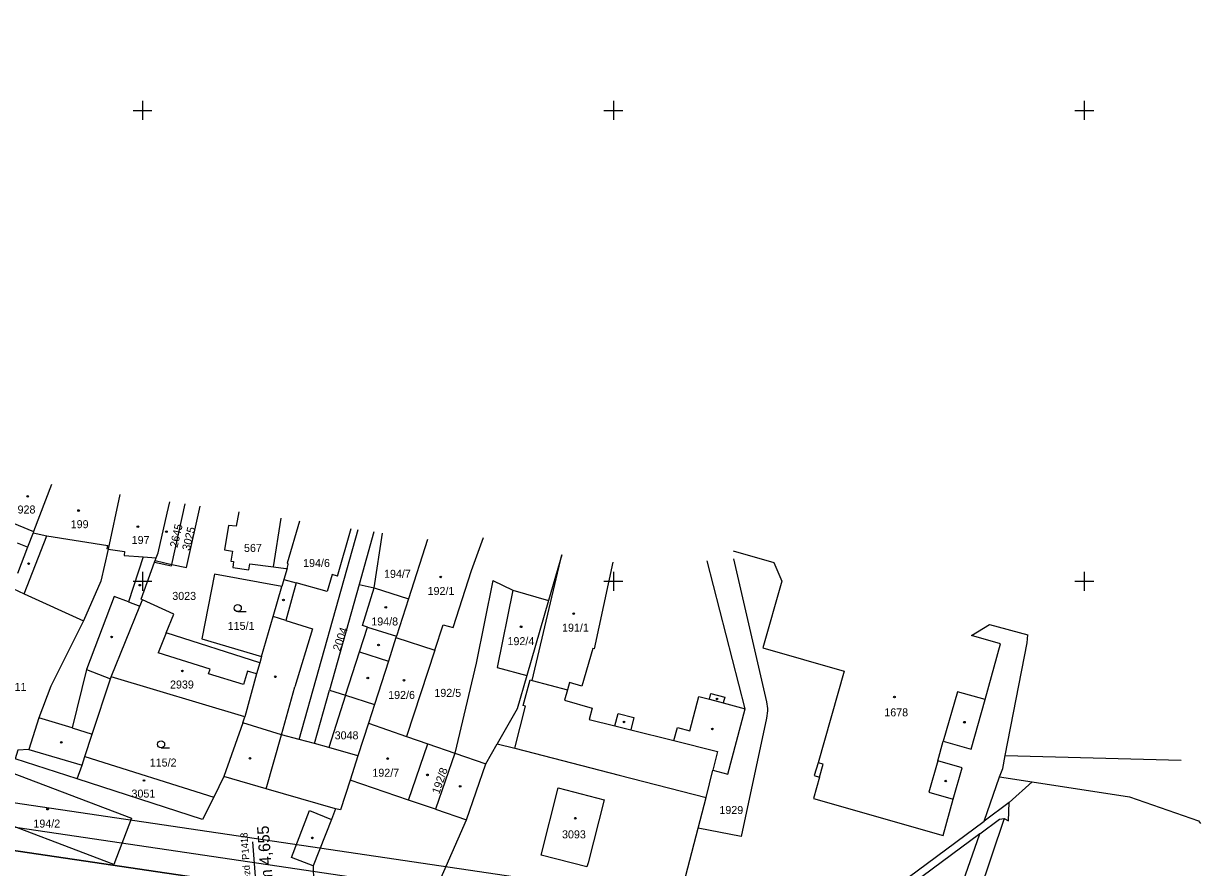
# Model space of a CAD drawing. Extents: x -779302 to -774398, y -1144902 to -1142831.
# Drawn here: x -774925.2 to -774675.3, y -1144360.8 to -1144181.6 of the extents above; entities that cross this region are included whole.
import ezdxf

# ---------------------------------------------------------------- set-up
doc = ezdxf.new("R2010")
doc.units = 0
for name, color, linetype in [('hektosit - Vrstva 5', 7, 'Continuous'), ('Hranice parcel', 7, 'Continuous'), ('Parcelní čísla', 7, 'Continuous'), ('Vnitřní kresba', 7, 'Continuous'), ('Vrstva 1', 7, 'Continuous'), ('zjednodus_g_situ-seda - Vrstva 4', 7, 'Continuous'), ('Značky budov', 7, 'Continuous'), ('Značky kultur', 7, 'Continuous')]:
    doc.layers.add(name, color=color, linetype=linetype)

msp = doc.modelspace()

# ---------------------------------------------------------------- linework, layer by layer
at = {"layer": 'hektosit - Vrstva 5'}
for p, q in [((-774900, -1144198), (-774900, -1144202)), ((-774800, -1144198), (-774800, -1144202)), ((-774700, -1144198), (-774700, -1144202)), ((-774902, -1144200), (-774898, -1144200)), ((-774802, -1144200), (-774798, -1144200)), ((-774702, -1144200), (-774698, -1144200)), ((-774900, -1144298), (-774900, -1144302)), ((-774800, -1144298), (-774800, -1144302)), ((-774700, -1144298), (-774700, -1144302)), ((-774902, -1144300), (-774898, -1144300)), ((-774802, -1144300), (-774798, -1144300)), ((-774702, -1144300), (-774698, -1144300))]:
    msp.add_line(p, q, dxfattribs=at)
at = {"layer": 'Hranice parcel'}
for p, q in [((-774893.78, -1144296.41), (-774890.92, -1144283.59)), ((-774866.73, -1144333.6), (-774854.2, -1144289.03)), ((-774850.85, -1144289.52), (-774853.99, -1144300.71)), ((-774839.44, -1144291.11), (-774843.52, -1144303.75)), ((-774810.96, -1144294.39), (-774813.77, -1144304.08)), ((-774853.99, -1144300.71), (-774860.29, -1144323.14)), ((-774846.16, -1144311.97), (-774837.89, -1144314.64)), ((-774837.89, -1144314.64), (-774843.96, -1144332.95)), ((-774874.7, -1144315.99), (-774875.08, -1144317.3)), ((-774878.28, -1144328.8), (-774906.64, -1144320.27)), ((-774863.47, -1144334.48), (-774860.29, -1144323.14)), ((-774850.74, -1144326.17), (-774852.02, -1144330.16)), ((-774878.71, -1144330.05), (-774878.28, -1144328.8)), ((-774852.02, -1144330.16), (-774854.24, -1144337.04)), ((-774852.02, -1144330.16), (-774843.96, -1144332.95)), ((-774863.47, -1144334.48), (-774866.73, -1144333.6)), ((-774843.96, -1144332.95), (-774839.41, -1144334.53)), ((-774843.47, -1144346.47), (-774839.41, -1144334.53)), ((-774839.41, -1144334.53), (-774833.68, -1144336.52)), ((-774912.2, -1144337.19), (-774884.85, -1144345.82)), ((-774854.24, -1144337.04), (-774855.92, -1144342.24)), ((-774716.78, -1144337.02), (-774679.41, -1144338.01)), ((-774913.86, -1144341.97), (-774927, -1144337.72)), ((-774843.47, -1144346.47), (-774855.92, -1144342.24)), ((-774721.28, -1144350.96), (-774718.02, -1144341.55)), ((-774782, -1144352.41), (-774780.31, -1144345.89))]:
    msp.add_line(p, q, dxfattribs=at)
for points in [[(-774919.28, -1144279.44), (-774923.12, -1144289.46), (-774923.21, -1144289.71), (-774924.38, -1144292.76), (-774926.52, -1144298.36)], [(-774904.78, -1144281.6), (-774907.28, -1144293.19), (-774908.84, -1144299.98), (-774912.54, -1144308.38)], [(-774897.4, -1144295.94), (-774897.28, -1144295.62), (-774897.07, -1144295.04), (-774896.68, -1144293.96), (-774894.72, -1144285.56), (-774894.18, -1144283.12)], [(-774893.78, -1144296.41), (-774890.67, -1144297.11), (-774887.75, -1144284.05)], [(-774879.56, -1144285.28), (-774880.06, -1144288.28), (-774881.72, -1144288.14), (-774882.56, -1144293.33), (-774880.89, -1144293.6), (-774881.2, -1144295.73), (-774880.63, -1144295.81), (-774880.81, -1144297.08), (-774877.38, -1144297.6), (-774877.2, -1144296.27), (-774872.18, -1144296.96), (-774869.53, -1144297.29), (-774869.28, -1144297.32)], [(-774869.28, -1144297.32), (-774869.02, -1144296.42), (-774869.19, -1144296.07), (-774866.6, -1144287.19)], [(-774837.89, -1144314.64), (-774836.11, -1144309.23), (-774834.01, -1144309.82), (-774830.14, -1144297.71), (-774827.58, -1144290.74)], [(-774774.57, -1144293.53), (-774765.9, -1144296.02), (-774764.22, -1144299.97), (-774768.29, -1144314.14), (-774750.98, -1144319.11), (-774756.51, -1144338.56), (-774757.38, -1144341.25), (-774756.2, -1144341.59), (-774757.5, -1144346.11), (-774730, -1144353.97), (-774727.82, -1144346.25), (-774725.92, -1144339.62), (-774731.12, -1144338.14), (-774729.94, -1144333.99), (-774724.02, -1144335.67), (-774721.09, -1144325.13), (-774717.77, -1144313.27), (-774723.95, -1144311.51), (-774720.12, -1144309.16), (-774712, -1144311.41)], [(-774900.01, -1144303.91), (-774900.24, -1144303.82), (-774897.4, -1144295.94)], [(-774897.4, -1144295.94), (-774893.86, -1144296.73), (-774893.78, -1144296.41)], [(-774774.48, -1144295.25), (-774767.47, -1144325.61), (-774767.27, -1144327.04), (-774767.26, -1144327.55), (-774767.48, -1144329.1), (-774772.89, -1144354.17), (-774782, -1144352.41)], [(-774780.31, -1144345.89), (-774778.87, -1144340.14), (-774775.69, -1144340.97), (-774772.03, -1144327.08), (-774780.09, -1144295.65)], [(-774870.37, -1144301.08), (-774884.68, -1144298.48), (-774887.41, -1144312.22), (-774874.7, -1144315.99)], [(-774869.28, -1144297.32), (-774869.95, -1144299.63), (-774870.37, -1144301.08)], [(-774927.54, -1144301.56), (-774925.13, -1144302.69), (-774912.54, -1144308.38)], [(-774874.7, -1144315.99), (-774872.23, -1144307.48), (-774870.37, -1144301.08)], [(-774853.99, -1144300.71), (-774850.78, -1144301.42), (-774843.52, -1144303.75)], [(-774825.63, -1144299.86), (-774829.16, -1144317.4), (-774833.68, -1144336.52)], [(-774825.63, -1144299.86), (-774821.36, -1144301.89), (-774813.77, -1144304.08)], [(-774906.64, -1144320.27), (-774900.57, -1144305.31), (-774900.01, -1144303.91)], [(-774875.08, -1144317.3), (-774894.95, -1144310.97), (-774893.3, -1144306.99), (-774900.01, -1144303.91)], [(-774843.52, -1144303.75), (-774846.07, -1144311.68), (-774846.16, -1144311.97)], [(-774813.77, -1144304.08), (-774818.37, -1144320.02), (-774820.43, -1144327.09), (-774824.66, -1144334.51)], [(-774912.54, -1144308.38), (-774919.42, -1144322.31), (-774922.03, -1144328.99), (-774924.14, -1144335.71), (-774926.42, -1144335.89), (-774927, -1144337.72)], [(-774846.16, -1144311.97), (-774847.76, -1144316.94), (-774850.74, -1144326.17)], [(-774716.78, -1144337.02), (-774712.11, -1144313.08), (-774712, -1144311.41)], [(-774875.08, -1144317.3), (-774875.75, -1144319.63), (-774878.28, -1144328.8)], [(-774912.2, -1144337.19), (-774910.64, -1144332.46), (-774906.8, -1144320.74), (-774906.64, -1144320.27)], [(-774860.29, -1144323.14), (-774856.87, -1144324.2), (-774850.74, -1144326.17)], [(-774878.71, -1144330.05), (-774882.69, -1144341.48), (-774884.85, -1144345.82)], [(-774866.73, -1144333.6), (-774870.5, -1144332.58), (-774878.71, -1144330.05)], [(-774854.24, -1144337.04), (-774860.45, -1144335.29), (-774863.47, -1144334.48)], [(-774845.62, -1144383.56), (-774831.16, -1144350.65), (-774827.09, -1144338.8), (-774824.66, -1144334.51)], [(-774824.66, -1144334.51), (-774820.92, -1144335.47), (-774798.77, -1144341.16), (-774780.31, -1144345.89)], [(-774913.86, -1144341.97), (-774912.82, -1144339.08), (-774912.2, -1144337.19)], [(-774833.68, -1144336.52), (-774837.74, -1144348.41), (-774843.47, -1144346.47)], [(-774718.02, -1144341.55), (-774717.33, -1144339.74), (-774716.78, -1144337.02)], [(-774902.35, -1144350.28), (-774906.07, -1144360.14), (-774935.48, -1144349), (-774931.84, -1144339.13), (-774902.35, -1144350.28)], [(-774884.85, -1144345.82), (-774887.22, -1144350.6), (-774913.86, -1144341.97)], [(-774855.92, -1144342.24), (-774857.95, -1144348.55), (-774858.99, -1144348.34), (-774859.86, -1144350.58), (-774863.72, -1144360.44), (-774863.41, -1144376.75), (-774845.62, -1144383.56)], [(-774718.02, -1144341.55), (-774711.1, -1144342.61), (-774690.44, -1144345.78), (-774675.74, -1144350.91), (-774675.34, -1144351.41)], [(-774805.38, -1144359.83), (-774805.62, -1144360.66), (-774815.36, -1144358.16), (-774811.7, -1144343.89), (-774801.96, -1144346.39), (-774805.38, -1144359.83)], [(-774722.22, -1144353.64), (-774717.98, -1144350.5), (-774717.01, -1144350.41), (-774716.11, -1144350.89), (-774715.95, -1144347), (-774721.28, -1144350.96)], [(-774801.98, -1144406.47), (-774799.57, -1144406.26), (-774796.3, -1144405.69), (-774793.89, -1144404.6), (-774791.79, -1144403.24), (-774759.55, -1144379.36), (-774721.28, -1144350.96)], [(-774722.22, -1144353.64), (-774758.58, -1144380.6), (-774790.75, -1144404.47), (-774793.02, -1144405.95), (-774795.8, -1144407.18), (-774799.56, -1144407.9), (-774820.31, -1144409.63), (-774822.18, -1144410.3), (-774823.4, -1144411.16), (-774824.38, -1144412.31), (-774825.86, -1144415.63)], [(-774804.69, -1144399.57), (-774793.9, -1144398.06), (-774782, -1144352.41)], [(-774739.17, -1144384.29), (-774735.41, -1144376.57), (-774726.72, -1144366.58), (-774722.22, -1144353.64)]]:
    msp.add_lwpolyline(points, dxfattribs=at)
at = {"layer": 'Vnitřní kresba'}
for p, q in [((-774929.64, -1144286.74), (-774923.12, -1144289.46)), ((-774872.18, -1144296.96), (-774870.57, -1144286.6)), ((-774923.21, -1144289.71), (-774920.27, -1144290.35)), ((-774858.55, -1144298.94), (-774855.71, -1144288.79)), ((-774850.78, -1144301.42), (-774849.03, -1144289.78)), ((-774924.38, -1144292.76), (-774926.53, -1144291.93)), ((-774925.13, -1144302.69), (-774920.27, -1144290.35)), ((-774920.27, -1144290.35), (-774907.36, -1144292.41)), ((-774907.5, -1144293.14), (-774907.36, -1144292.41)), ((-774907.28, -1144293.19), (-774907.5, -1144293.14)), ((-774907.28, -1144293.19), (-774903.81, -1144293.67)), ((-774903.81, -1144293.67), (-774903.87, -1144294.52)), ((-774903.87, -1144294.52), (-774899.85, -1144294.83)), ((-774817.22, -1144321.04), (-774810.96, -1144294.39)), ((-774899.85, -1144294.83), (-774902.94, -1144304.4)), ((-774899.85, -1144294.83), (-774897.07, -1144295.04)), ((-774897.28, -1144295.62), (-774893.78, -1144296.41)), ((-774800.08, -1144295.92), (-774804.08, -1144314.36)), ((-774869.95, -1144299.63), (-774867.32, -1144300.36)), ((-774859.68, -1144298.59), (-774860.74, -1144302.2)), ((-774858.55, -1144298.94), (-774859.68, -1144298.59)), ((-774867.32, -1144300.36), (-774869.56, -1144308.32)), ((-774860.74, -1144302.2), (-774867.32, -1144300.36)), ((-774853.3, -1144309.42), (-774850.78, -1144301.42)), ((-774821.36, -1144301.89), (-774824.66, -1144318.3)), ((-774906.01, -1144303.22), (-774911.9, -1144318.72)), ((-774902.94, -1144304.4), (-774906.01, -1144303.22)), ((-774902.94, -1144304.4), (-774900.57, -1144305.31)), ((-774869.56, -1144308.32), (-774872.23, -1144307.48)), ((-774869.56, -1144308.32), (-774863.86, -1144310.11)), ((-774853.88, -1144314.97), (-774852.2, -1144309.76)), ((-774852.2, -1144309.76), (-774853.3, -1144309.42)), ((-774852.2, -1144309.76), (-774846.07, -1144311.68)), ((-774894.95, -1144310.97), (-774896.69, -1144315.17)), ((-774863.86, -1144310.11), (-774867.63, -1144322.44)), ((-774804.37, -1144314.28), (-774806.72, -1144322.27)), ((-774804.08, -1144314.36), (-774804.37, -1144314.28)), ((-774885.65, -1144318.69), (-774896.69, -1144315.17)), ((-774856.87, -1144324.2), (-774853.88, -1144314.97)), ((-774853.88, -1144314.97), (-774847.76, -1144316.94)), ((-774911.9, -1144318.72), (-774914.95, -1144331.15)), ((-774911.9, -1144318.72), (-774906.8, -1144320.74)), ((-774885.95, -1144319.64), (-774885.65, -1144318.69)), ((-774878.55, -1144321.92), (-774885.95, -1144319.64)), ((-774877.72, -1144319.06), (-774878.55, -1144321.92)), ((-774875.75, -1144319.63), (-774877.72, -1144319.06)), ((-774824.66, -1144318.3), (-774818.37, -1144320.02)), ((-774819.12, -1144326.38), (-774817.7, -1144320.92)), ((-774817.7, -1144320.92), (-774817.22, -1144321.04)), ((-774817.22, -1144321.04), (-774809.77, -1144323.09)), ((-774809.33, -1144321.5), (-774809.77, -1144323.09)), ((-774806.72, -1144322.27), (-774809.33, -1144321.5)), ((-774870.5, -1144332.58), (-774867.63, -1144322.44)), ((-774856.87, -1144324.2), (-774860.45, -1144335.29)), ((-774809.77, -1144323.09), (-774810.37, -1144325.28)), ((-774783.77, -1144331.76), (-774781.84, -1144324.48)), ((-774781.84, -1144324.48), (-774779.61, -1144325.07)), ((-774779.61, -1144325.07), (-774779.28, -1144323.81)), ((-774779.28, -1144323.81), (-774776.36, -1144324.58)), ((-774776.36, -1144324.58), (-774776.7, -1144325.84)), ((-774726.96, -1144323.49), (-774729.94, -1144333.99)), ((-774721.09, -1144325.13), (-774726.96, -1144323.49)), ((-774820.92, -1144335.47), (-774818.63, -1144326.51)), ((-774818.63, -1144326.51), (-774819.12, -1144326.38)), ((-774810.37, -1144325.28), (-774804.47, -1144326.92)), ((-774804.47, -1144326.92), (-774805.13, -1144329.38)), ((-774779.61, -1144325.07), (-774776.7, -1144325.84)), ((-774776.7, -1144325.84), (-774772.03, -1144327.08)), ((-774914.95, -1144331.15), (-774922.03, -1144328.99)), ((-774805.13, -1144329.38), (-774799.66, -1144330.73)), ((-774799.66, -1144330.73), (-774799, -1144328.05)), ((-774799, -1144328.05), (-774795.66, -1144328.94)), ((-774795.66, -1144328.94), (-774796.31, -1144331.56)), ((-774914.95, -1144331.15), (-774910.64, -1144332.46)), ((-774799.66, -1144330.73), (-774796.31, -1144331.56)), ((-774796.31, -1144331.56), (-774787.13, -1144333.84)), ((-774787.13, -1144333.84), (-774786.4, -1144331.07)), ((-774786.4, -1144331.07), (-774783.77, -1144331.76)), ((-774873.73, -1144344.05), (-774870.5, -1144332.58)), ((-774787.13, -1144333.84), (-774777.87, -1144336.13)), ((-774924.14, -1144335.71), (-774912.82, -1144339.08)), ((-774833.68, -1144336.52), (-774827.09, -1144338.8)), ((-774777.87, -1144336.13), (-774778.87, -1144340.14)), ((-774755.42, -1144338.87), (-774756.51, -1144338.56)), ((-774756.2, -1144341.59), (-774755.42, -1144338.87)), ((-774731.12, -1144338.14), (-774733, -1144344.78)), ((-774873.73, -1144344.05), (-774882.69, -1144341.48)), ((-774858.99, -1144348.34), (-774873.73, -1144344.05)), ((-774715.95, -1144347), (-774711.1, -1144342.61)), ((-774733, -1144344.78), (-774727.82, -1144346.25)), ((-774868.38, -1144358.66), (-774864.54, -1144348.65)), ((-774864.54, -1144348.65), (-774859.86, -1144350.58)), ((-774837.74, -1144348.41), (-774831.16, -1144350.65)), ((-774717.01, -1144350.41), (-774727.14, -1144380.18)), ((-774863.72, -1144360.44), (-774868.38, -1144358.66))]:
    msp.add_line(p, q, dxfattribs=at)
at = {"layer": 'Vrstva 1'}
for points in [[(-774799.29, -1144366.04), (-776045.7, -1144181.56), (-776089.18, -1144475.34), (-774842.77, -1144659.83)], [(-774846.98, -1144654.15), (-776083.5, -1144471.13), (-776041.48, -1144187.23), (-774804.97, -1144370.25)], [(-774810.64, -1144374.46), (-775834.48, -1144222.92), (-775875.04, -1144496.94), (-774851.19, -1144648.48)], [(-774851.19, -1144648.48), (-775875.04, -1144496.94), (-775834.48, -1144222.92), (-774810.64, -1144374.46)]]:
    msp.add_lwpolyline(points, close=True, dxfattribs=at)
at = {"layer": 'zjednodus_g_situ-seda - Vrstva 4'}
msp.add_line((-774870.87, -1144434.54), (-774876.52, -1144355.31), dxfattribs=at)
at = {"layer": 'Značky budov'}
for centre in [(-774924.36, -1144281.97), (-774913.57, -1144284.98), (-774900.96, -1144288.39), (-774894.9, -1144289.46), (-774924.17, -1144296.26), (-774836.66, -1144299.09), (-774900.55, -1144300.83), (-774870.05, -1144303.97), (-774848.32, -1144305.52), (-774808.43, -1144306.88), (-774819.59, -1144309.66), (-774906.54, -1144311.82), (-774849.86, -1144313.55), (-774891.52, -1144319.05), (-774871.78, -1144320.28), (-774852.15, -1144320.56), (-774844.46, -1144321.01), (-774740.31, -1144324.58), (-774777.99, -1144324.99), (-774797.74, -1144329.87), (-774725.46, -1144329.93), (-774778.97, -1144331.36), (-774917.23, -1144334.22), (-774877.17, -1144337.6), (-774847.92, -1144337.65), (-774899.68, -1144342.31), (-774839.48, -1144341.11), (-774729.44, -1144342.43), (-774832.53, -1144343.54), (-774920.15, -1144348.39), (-774808.09, -1144350.32), (-774863.92, -1144354.5)]:
    msp.add_circle(centre, 0.175, dxfattribs=at)
at = {"layer": 'Značky kultur'}
for p, q in [((-774879.75, -1144306.45), (-774878, -1144306.45)), ((-774896.03, -1144335.38), (-774894.28, -1144335.38))]:
    msp.add_line(p, q, dxfattribs=at)
for centre in [(-774879.75, -1144305.7), (-774896.03, -1144334.63)]:
    msp.add_circle(centre, 0.75, dxfattribs=at)

# ---------------------------------------------------------------- texts
at = {"layer": 'Parcelní čísla'}
for s, p in [('928', (-774926.51, -1144285.61)), ('199', (-774915.23, -1144288.73)), ('197', (-774902.28, -1144292.08)), ('567', (-774878.43, -1144293.77)), ('194/6', (-774865.88, -1144296.97)), ('194/7', (-774848.7, -1144299.27)), ('3023', (-774893.66, -1144303.96)), ('192/1', (-774839.45, -1144302.91)), ('115/1', (-774881.89, -1144310.32)), ('194/8', (-774851.4, -1144309.39)), ('191/1', (-774810.9, -1144310.7)), ('192/4', (-774822.48, -1144313.57)), ('111', (-774928.42, -1144323.28)), ('2939', (-774894.14, -1144322.78)), ('192/6', (-774847.82, -1144324.99)), ('192/5', (-774838.01, -1144324.55)), ('1678', (-774742.47, -1144328.69)), ('3048', (-774859.18, -1144333.57)), ('115/2', (-774898.44, -1144339.35)), ('192/7', (-774851.17, -1144341.51)), ('3051', (-774902.32, -1144345.94)), ('1929', (-774777.49, -1144349.43)), ('194/2', (-774923.15, -1144352.31)), ('3093', (-774810.9, -1144354.6))]:
    msp.add_text(s, height=1.7, dxfattribs=at).set_placement(p)
for s, rotation, p in [('2645', 77, (-774892.57, -1144292.97)), ('3025', 76, (-774889.97, -1144293.6)), ('2004', 71, (-774858.04, -1144314.94)), ('192/8', 71, (-774836.98, -1144345.31))]:
    msp.add_text(s, height=1.7, rotation=rotation, dxfattribs=at).set_placement(p)
at = {"layer": 'zjednodus_g_situ-seda - Vrstva 4'}
for s, height, p in [('evid. km 4,655', 2.5, (-774871.65, -1144373.52)), ('Přejezd  P1418', 1.5, (-774876.75, -1144367.01))]:
    msp.add_text(s, height=height, rotation=94.0794, dxfattribs=at).set_placement(p)

doc.saveas('drawing.dxf')
